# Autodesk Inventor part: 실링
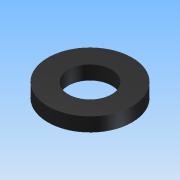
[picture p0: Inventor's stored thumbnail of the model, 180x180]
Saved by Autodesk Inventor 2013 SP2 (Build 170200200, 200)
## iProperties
Created: 2025-10
Part Number: 실링
Material: Generic
Document SubType Name: Modeling
Designer: a
Density: 1 g/cm^3
Author: a
변환 표준: STEP AP214IS
전처리기: Build: 200, Release: 2013 SP2 Update 6 - Date: Thu 07/17/2014
전송 단위: 밀리미터
불확실성: 0.01
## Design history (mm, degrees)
node "실링1"
node "솔리드1"
node "기준1"
